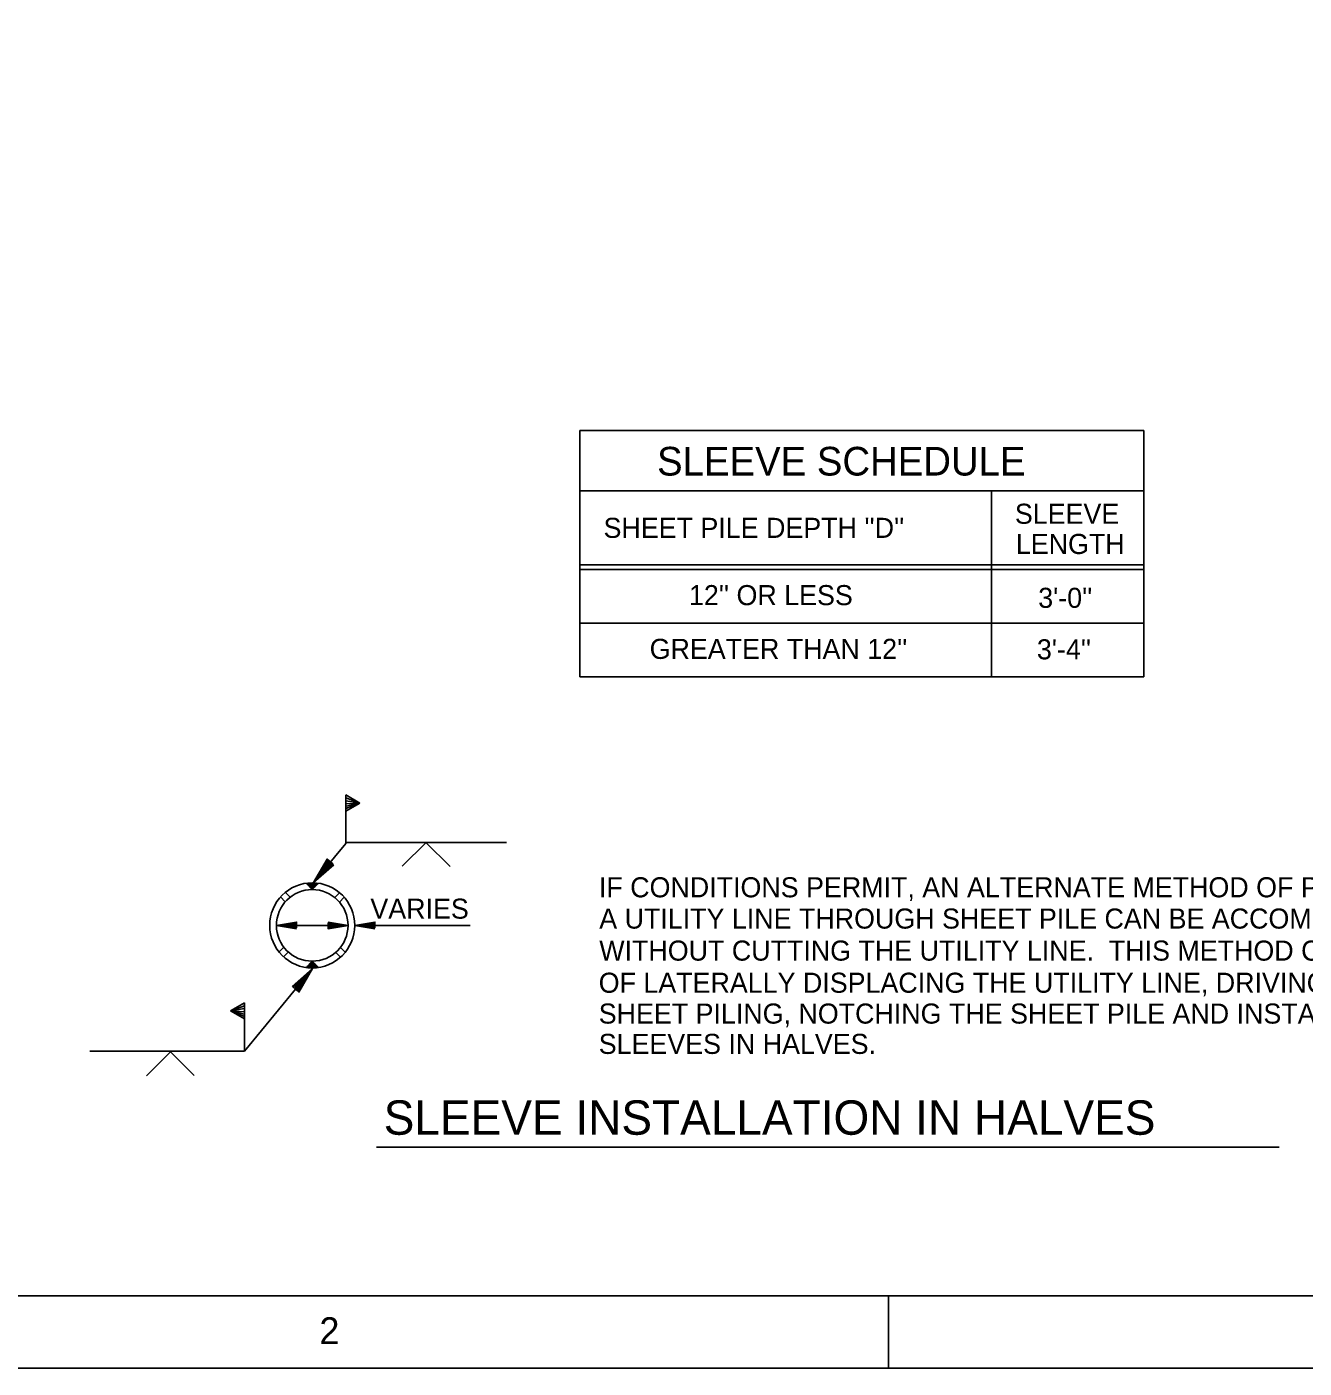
# Model space of a CAD drawing. Extents: x 22411.4 to 22495.4, y 22369.6 to 22415.
# Drawn here: x 22451.61 to 22463.5, y 22369.62 to 22382.1 of the extents above; entities that cross this region are included whole.
import ezdxf

# ---------------------------------------------------------------- set-up
doc = ezdxf.new("R2010")
doc.units = 0
for name, color, linetype in [('Level 1', 7, 'Continuous'), ('Level 10', 7, 'Continuous'), ('Level 2', 7, 'Continuous'), ('Level 3', 7, 'Continuous'), ('Level 4', 7, 'Continuous'), ('Level 7', 7, 'Continuous'), ('Level 9', 7, 'Continuous')]:
    doc.layers.add(name, color=color, linetype=linetype)

msp = doc.modelspace()

# ---------------------------------------------------------------- linework, layer by layer
at = {"layer": 'Level 1'}
for p, q in [((22454.323, 22374.192), (22454.323, 22374.192)), ((22454.279, 22374.139), (22454.279, 22374.139)), ((22454.016, 22373.96), (22453.972, 22374.005)), ((22454.062, 22374.003), (22454.017, 22374.048)), ((22454.476, 22374.001), (22454.521, 22374.045)), ((22454.521, 22373.957), (22454.565, 22374.002)), ((22453.934, 22373.741), (22454.601, 22373.741)), ((22453.934, 22373.741), (22453.934, 22373.741)), ((22453.986, 22373.741), (22453.986, 22373.741)), ((22454.549, 22373.741), (22454.549, 22373.741)), ((22454.601, 22373.741), (22454.601, 22373.741)), ((22454.663, 22373.741), (22455.736, 22373.741)), ((22454.663, 22373.741), (22454.663, 22373.741)), ((22454.715, 22373.741), (22454.715, 22373.741)), ((22453.958, 22373.495), (22454.002, 22373.539)), ((22454, 22373.449), (22454.044, 22373.493)), ((22454.531, 22373.446), (22454.487, 22373.49)), ((22454.574, 22373.491), (22454.53, 22373.535)), ((22454.27, 22373.339), (22454.27, 22373.339)), ((22454.226, 22373.286), (22454.226, 22373.286))]:
    msp.add_line(p, q, dxfattribs=at)
msp.add_lwpolyline([(22436.723, 22414.965), (22495.39, 22414.965), (22495.39, 22369.621), (22436.723, 22369.621)], close=True, dxfattribs=at)
for points in [[(22454.121, 22373.71), (22453.934, 22373.741), (22454.121, 22373.772), (22454.121, 22373.719), (22453.986, 22373.741), (22454.113, 22373.762), (22454.113, 22373.728), (22454.036, 22373.741), (22454.105, 22373.752), (22454.105, 22373.738), (22454.088, 22373.741)], [(22454.414, 22373.772), (22454.601, 22373.741), (22454.414, 22373.71), (22454.414, 22373.763), (22454.549, 22373.741), (22454.422, 22373.72), (22454.422, 22373.754), (22454.499, 22373.741), (22454.43, 22373.73), (22454.43, 22373.744), (22454.447, 22373.741)], [(22454.85, 22373.71), (22454.663, 22373.741), (22454.85, 22373.772), (22454.85, 22373.719), (22454.715, 22373.741), (22454.842, 22373.762), (22454.842, 22373.728), (22454.765, 22373.741), (22454.834, 22373.752), (22454.834, 22373.738), (22454.817, 22373.741)]]:
    msp.add_lwpolyline(points, dxfattribs=at)
at = {"layer": 'Level 10'}
for p, q in [((22454.58, 22374.504), (22454.58, 22374.954)), ((22454.58, 22374.954), (22454.71, 22374.879)), ((22454.71, 22374.879), (22454.58, 22374.926)), ((22454.71, 22374.879), (22454.58, 22374.901)), ((22454.71, 22374.879), (22454.58, 22374.804)), ((22454.71, 22374.879), (22454.58, 22374.829)), ((22454.71, 22374.879), (22454.582, 22374.85)), ((22454.71, 22374.879), (22454.587, 22374.873)), ((22454.279, 22374.139), (22454.58, 22374.504)), ((22454.575, 22374.513), (22456.076, 22374.513)), ((22455.326, 22374.513), (22455.104, 22374.291)), ((22455.325, 22374.513), (22455.549, 22374.289)), ((22453.636, 22372.57), (22454.27, 22373.339)), ((22453.636, 22373.02), (22453.506, 22372.945)), ((22453.506, 22372.945), (22453.636, 22372.992)), ((22453.506, 22372.945), (22453.636, 22372.966)), ((22453.506, 22372.945), (22453.636, 22372.87)), ((22453.506, 22372.945), (22453.629, 22372.938)), ((22453.506, 22372.945), (22453.634, 22372.915)), ((22453.506, 22372.945), (22453.636, 22372.894)), ((22453.636, 22372.57), (22453.636, 22372.839)), ((22453.636, 22372.57), (22452.198, 22372.57)), ((22452.947, 22372.565), (22452.724, 22372.342)), ((22452.947, 22372.565), (22453.168, 22372.343)), ((22454.866, 22371.676), (22463.266, 22371.676)), ((22459.63, 22369.621), (22459.63, 22370.293))]:
    msp.add_line(p, q, dxfattribs=at)
for points in [[(22454.469, 22374.305), (22454.279, 22374.139), (22454.405, 22374.358), (22454.46, 22374.313), (22454.323, 22374.192), (22454.409, 22374.341), (22454.444, 22374.312), (22454.365, 22374.244), (22454.412, 22374.324), (22454.427, 22374.312), (22454.409, 22374.297)], [(22454.08, 22373.173), (22454.27, 22373.339), (22454.143, 22373.12), (22454.089, 22373.165), (22454.226, 22373.286), (22454.14, 22373.137), (22454.105, 22373.166), (22454.184, 22373.234), (22454.136, 22373.154), (22454.122, 22373.166), (22454.139, 22373.181)]]:
    msp.add_lwpolyline(points, dxfattribs=at)
at = {"layer": 'Level 2'}
for p, q in [((22456.756, 22377.094), (22462.006, 22377.094)), ((22456.756, 22377.052), (22462.006, 22377.052)), ((22456.756, 22376.552), (22462.006, 22376.552)), ((22454.267, 22374.074), (22454.209, 22374.133)), ((22454.267, 22374.074), (22454.326, 22374.133)), ((22454.267, 22373.408), (22454.209, 22373.35)), ((22454.267, 22373.408), (22454.326, 22373.35))]:
    msp.add_line(p, q, dxfattribs=at)
for points in [[(22454.21, 22374.132), (22454.324, 22374.132)], [(22454.221, 22374.121), (22454.314, 22374.121)], [(22454.231, 22374.111), (22454.304, 22374.111)], [(22454.242, 22374.1), (22454.293, 22374.1)], [(22454.252, 22374.09), (22454.283, 22374.09)], [(22454.262, 22374.08), (22454.272, 22374.08)], [(22454.217, 22373.358), (22454.317, 22373.358)], [(22454.228, 22373.368), (22454.307, 22373.368)], [(22454.229, 22373.347), (22454.307, 22373.347)], [(22454.238, 22373.379), (22454.297, 22373.379)], [(22454.249, 22373.389), (22454.286, 22373.389)], [(22454.259, 22373.399), (22454.276, 22373.399)]]:
    msp.add_lwpolyline(points, dxfattribs=at)
for radius in [0.396, 0.333]:
    msp.add_circle((22454.267, 22373.741), radius, dxfattribs=at)
at = {"layer": 'Level 3'}
for p, q in [((22454.267, 22374.074), (22454.267, 22374.074)), ((22454.267, 22373.741), (22454.267, 22373.741))]:
    msp.add_line(p, q, dxfattribs=at)
at = {"layer": 'Level 4'}
msp.add_line((22453.636, 22372.839), (22453.636, 22373.02), dxfattribs=at)
at = {"layer": 'Level 7'}
for p, q in [((22456.756, 22378.345), (22462.006, 22378.345)), ((22456.756, 22376.052), (22456.756, 22378.345)), ((22462.006, 22376.052), (22462.006, 22378.345)), ((22456.756, 22377.783), (22462.006, 22377.783)), ((22460.589, 22376.052), (22460.589, 22377.783)), ((22456.756, 22376.052), (22462.006, 22376.052)), ((22455.326, 22374.513), (22455.326, 22374.513)), ((22452.946, 22372.565), (22452.947, 22372.565))]:
    msp.add_line(p, q, dxfattribs=at)
at = {"layer": 'Level 9'}
msp.add_line((22438.723, 22370.293), (22491.054, 22370.293), dxfattribs=at)

# ---------------------------------------------------------------- texts
at = {"layer": 'Level 1'}
msp.add_text('2', height=0.25, dxfattribs=at).set_placement((22454.334, 22369.845))
at = {"layer": 'Level 3'}
msp.add_text('SLEEVE INSTALLATION IN HALVES', height=0.32, dxfattribs=at).set_placement((22454.932, 22371.793))
at = {"layer": 'Level 4'}
for s, height, p in [('SLEEVE SCHEDULE', 0.2667, (22457.476, 22377.926)), ('SLEEVE', 0.1867, (22460.806, 22377.477)), ("SHEET PILE DEPTH ''D''", 0.1867, (22456.978, 22377.346)), ('LENGTH', 0.1867, (22460.815, 22377.196)), ("12'' OR LESS", 0.1867, (22457.773, 22376.72)), ("3'-0''", 0.1867, (22461.023, 22376.695)), ("GREATER THAN 12''", 0.1867, (22457.407, 22376.22)), ("3'-4''", 0.1867, (22461.011, 22376.216)), ('IF CONDITIONS PERMIT, AN ALTERNATE METHOD OF PASSING', 0.18667, (22456.935, 22374.002)), ('VARIES', 0.1867, (22454.808, 22373.803)), ('A UTILITY LINE THROUGH SHEET PILE CAN BE ACCOMPLISHED', 0.18667, (22456.938, 22373.711)), ('WITHOUT CUTTING THE UTILITY LINE.  THIS METHOD CONSIST', 0.18667, (22456.938, 22373.413)), ('OF LATERALLY DISPLACING THE UTILITY LINE, DRIVING THE', 0.18667, (22456.933, 22373.114)), ('SHEET PILING, NOTCHING THE SHEET PILE AND INSTALLING', 0.18667, (22456.933, 22372.827)), ('SLEEVES IN HALVES.', 0.18667, (22456.933, 22372.545))]:
    msp.add_text(s, height=height, dxfattribs=at).set_placement(p)

doc.saveas('drawing.dxf')
